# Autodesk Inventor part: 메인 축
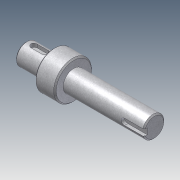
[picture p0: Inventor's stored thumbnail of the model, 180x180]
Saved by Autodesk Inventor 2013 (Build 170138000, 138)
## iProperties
Company: 한국ATC센터
Created: 2014-10
Part Number: 메인 축
Document SubType Name: Modeling
Designer: KYOUNG IL JANG
Density: 1 g/cm^3
Mass: 29.2926 g
Surface Area: 74.3518 cm^2
Volume: 29.2926 cm^3
Material: 일반
Author: KYOUNG IL JANG
Revision Number: 1
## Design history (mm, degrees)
sketch "스케치1"
  geometry: L1 (10.497, -57.5)-(112.497, -57.5); L2 (10.497, -66)-(32.497, -66); L3 (32.497, -72.5)-(46.5, -72.5); L4 (46.5, -66)-(112.497, -66); L5 (112.497, -66)-(112.497, -57.5); L6 (10.497, -66)-(10.497, -57.5); L7 (46.5, -69.749)-(46.5, -45.251) reference; L8 (46.5, -72.5)-(46.5, -66); L9 (32.497, -72.5)-(32.497, -66); L10 (32.497, -35)-(32.497, -80) reference; 3 further points
  constraints: 16 end point, 3 point on line, 2 parallel, 2 perpendicular, 1 collinear, 1 horizontal, 1 midpoint
  dimensions: "d0" = 17 diameter of L4 L1; "d1" = 30 diameter of L3 L1; "d2" = 22 distance of L2.start L2.end; "d3" = 65.99692 distance of L4.start L4.end (derived); "d5" = 17 diameter of L2 L1; "d19" = 80 distance between parallel lines of L5 L9
revolve "회전1" sketch "스케치1" stored, may be unused: angle "d4" = 90 deg
chamfer "모따기1" distance "d6" = 1; stored, may be unused: second distance "d7" = 2, angle "d8" = 45 deg
node "작업 평면1"
sketch "스케치2"
  geometry: L1 (-11, -7.5)-(-11, 7.5) reference; L2 (-4.5, 2.5)-(4.5, 2.5); L3 (4.5, -2.5)-(-4.5, -2.5); A1 r 2.5 centre (4.5, 0) between (4.5, -2.5) and (4.5, 2.5); A2 r 2.5 centre (-4.5, 0) between (-4.5, 2.5) and (-4.5, -2.5); 2 further points
  constraints: 4 end point, 4 point on circle, 4 tangent, 2 centre point, 1 horizontal alignment, 1 midpoint, 1 parallel, 1 perpendicular
  dimensions: "d9" = 5 distance between parallel lines of L3 L2; "d10" = 14 dimension on A1 A2; "d11" = 4 distance edge to line of A2 L1
extrude "돌출1" cut sketch "스케치2" distance "d12" = 3; taper "d13" = 0 deg
node "작업 평면2"
sketch "스케치3"
  geometry: L1 (32.998, 7.5)-(32.998, -7.5) reference; L2 (32.998, 2.5)-(17.498, 2.5); L3 (17.498, -2.5)-(32.998, -2.5); A1 r 2.5 centre (17.498, 0) between (17.498, 2.5) and (17.498, -2.5); 2 further points
  constraints: 4 end point, 2 perpendicular, 2 point on circle, 2 point on line, 2 tangent, 1 centre point, 1 horizontal alignment, 1 midpoint
  dimensions: "d14" = 5 distance between parallel lines of L3 L2; "d15" = 18 dimension on A1 L1
extrude "돌출2" cut sketch "스케치3" distance "d16" = 3; taper "d17" = 0 deg
node "솔리드1"
node "참조4"
node "참조5"
